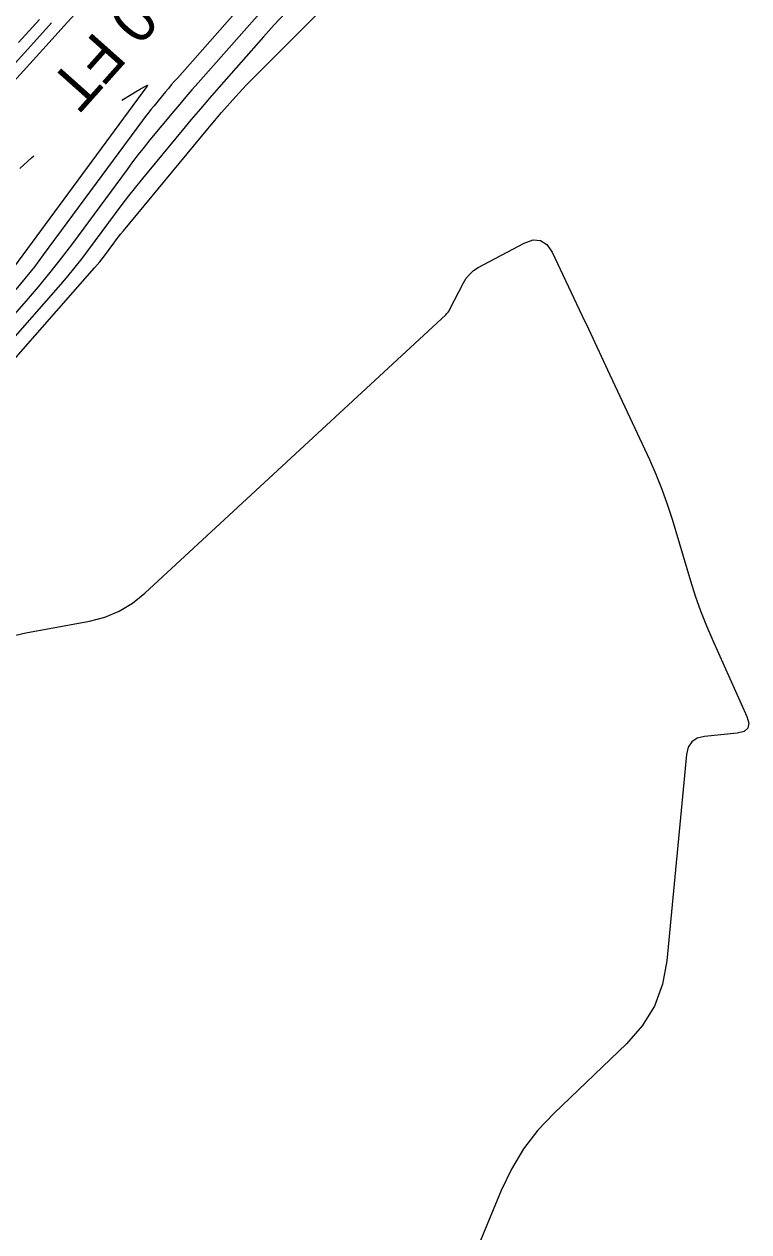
# Model space of a CAD drawing. Extents: x 1768942 to 1774819, y 723037 to 732099.
# Drawn here: x 1771433.6 to 1771531.9, y 724942 to 725105.7 of the extents above; entities that cross this region are included whole.
import ezdxf

# ---------------------------------------------------------------- set-up
doc = ezdxf.new("R2010")
doc.units = 0
doc.layers.add('R_Contour Annot', color=7, linetype='Continuous')
doc.layers.add('R_Contours', color=7, linetype='Continuous')

msp = doc.modelspace()

# ---------------------------------------------------------------- linework, layer by layer
at = {"layer": 'R_Contours'}
for points in [[(1771416.7, 725042.55), (1771443.15, 725072.64), (1771443.5, 725073.04), (1771443.84, 725073.45), (1771444.17, 725073.86), (1771444.48, 725074.29), (1771445.74, 725075.99), (1771446.06, 725076.42), (1771446.39, 725076.84), (1771446.71, 725077.25), (1771447.05, 725077.66), (1771458.5, 725091.49), (1771458.96, 725092.04), (1771459.43, 725092.59), (1771459.9, 725093.14), (1771460.37, 725093.68), (1771462.28, 725095.84), (1771462.76, 725096.37), (1771463.25, 725096.9), (1771463.74, 725097.42), (1771464.25, 725097.93), (1771492.76, 725126.46)], [(1771479.08, 725126.33), (1771454.36, 725098.36), (1771453.95, 725097.89), (1771453.54, 725097.42), (1771453.14, 725096.95), (1771452.75, 725096.47), (1771451.16, 725094.56), (1771450.77, 725094.09), (1771450.39, 725093.6), (1771450.01, 725093.11), (1771449.64, 725092.61), (1771436.18, 725074.39), (1771434.98, 725072.8), (1771433.74, 725071.23), (1771432.47, 725069.69)], [(1771471.41, 725113.82), (1771457.17, 725097.71), (1771456.34, 725096.76), (1771455.51, 725095.81), (1771454.69, 725094.84), (1771453.88, 725093.87), (1771450.65, 725089.97), (1771449.85, 725088.99), (1771449.07, 725088), (1771448.3, 725087), (1771447.54, 725085.99), (1771440.13, 725075.95), (1771438.62, 725073.96), (1771437.07, 725072), (1771435.49, 725070.07), (1771433.86, 725068.17), (1771424.75, 725057.81)], [(1771468.98, 725107.15), (1771467.51, 725105.56), (1771466.06, 725103.95), (1771459.99, 725097.07), (1771458.73, 725095.64), (1771457.48, 725094.19), (1771456.24, 725092.73), (1771455.02, 725091.27), (1771449.64, 725084.77), (1771448.68, 725083.59), (1771447.74, 725082.41), (1771446.82, 725081.21), (1771445.91, 725080), (1771442.31, 725075.12), (1771441.39, 725073.91), (1771440.46, 725072.72), (1771439.49, 725071.55), (1771438.5, 725070.41), (1771420.97, 725050.46)], [(1771440.94, 725107.55), (1771438.97, 725105.37), (1771436.99, 725103.19), (1771427.37, 725092.59)], [(1771437.32, 725105.84), (1771434.9, 725103.18), (1771421.77, 725088.7)], [(1771435.66, 725106.31), (1771432.81, 725103.16)], [(1771446.82, 725095.35), (1771448.93, 725096.63), (1771449.08, 725096.72), (1771449.23, 725096.81), (1771449.38, 725096.89), (1771449.54, 725096.98), (1771450.14, 725097.32), (1771450.26, 725097.38), (1771450.32, 725097.38), (1771450.31, 725097.32), (1771450.24, 725097.21), (1771431.49, 725071.82)], [(1771433.02, 725086.1), (1771434.6, 725087.55), (1771434.92, 725087.8)], [(1771431.71, 725022.7), (1771433.81, 725023.21), (1771442.43, 725024.79), (1771444.52, 725025.33), (1771446.46, 725026.13), (1771448.28, 725027.21), (1771449.95, 725028.56), (1771490.75, 725066.28), (1771490.92, 725066.45), (1771491.07, 725066.63), (1771491.2, 725066.82), (1771491.32, 725067.03), (1771493.15, 725070.62), (1771493.54, 725071.25), (1771494, 725071.8), (1771494.54, 725072.27), (1771495.17, 725072.67), (1771501.41, 725075.99), (1771502.59, 725076.42), (1771503.61, 725076.35), (1771504.47, 725075.8), (1771505.17, 725074.75), (1771509.21, 725066.24), (1771510.09, 725064.39), (1771510.96, 725062.54), (1771511.83, 725060.69), (1771512.7, 725058.84), (1771518.37, 725046.66), (1771519.25, 725044.68), (1771520.06, 725042.67), (1771520.79, 725040.63), (1771521.44, 725038.57), (1771523.92, 725030.25), (1771524.58, 725028.19), (1771525.3, 725026.15), (1771526.09, 725024.13), (1771526.95, 725022.14), (1771531.59, 725011.85), (1771531.85, 725010.94), (1771531.72, 725010.26), (1771531.2, 725009.81), (1771530.29, 725009.59), (1771525.84, 725009.15), (1771524.85, 725008.91), (1771524.12, 725008.43), (1771523.63, 725007.69), (1771523.4, 725006.7), (1771520.72, 724978.77), (1771520.14, 724975.57), (1771519.04, 724972.62), (1771517.41, 724969.93), (1771515.25, 724967.5), (1771505.46, 724958.12), (1771503.25, 724955.79), (1771501.31, 724953.26), (1771499.66, 724950.54), (1771498.27, 724947.64), (1771493.29, 724935.64)]]:
    msp.add_lwpolyline(points, dxfattribs=at)

# ---------------------------------------------------------------- texts
at = {"layer": 'R_Contour Annot'}
msp.add_text('290 FT', height=6, rotation=228.307, dxfattribs=at).set_placement((1771453.63, 725116.53))

doc.saveas('drawing.dxf')
